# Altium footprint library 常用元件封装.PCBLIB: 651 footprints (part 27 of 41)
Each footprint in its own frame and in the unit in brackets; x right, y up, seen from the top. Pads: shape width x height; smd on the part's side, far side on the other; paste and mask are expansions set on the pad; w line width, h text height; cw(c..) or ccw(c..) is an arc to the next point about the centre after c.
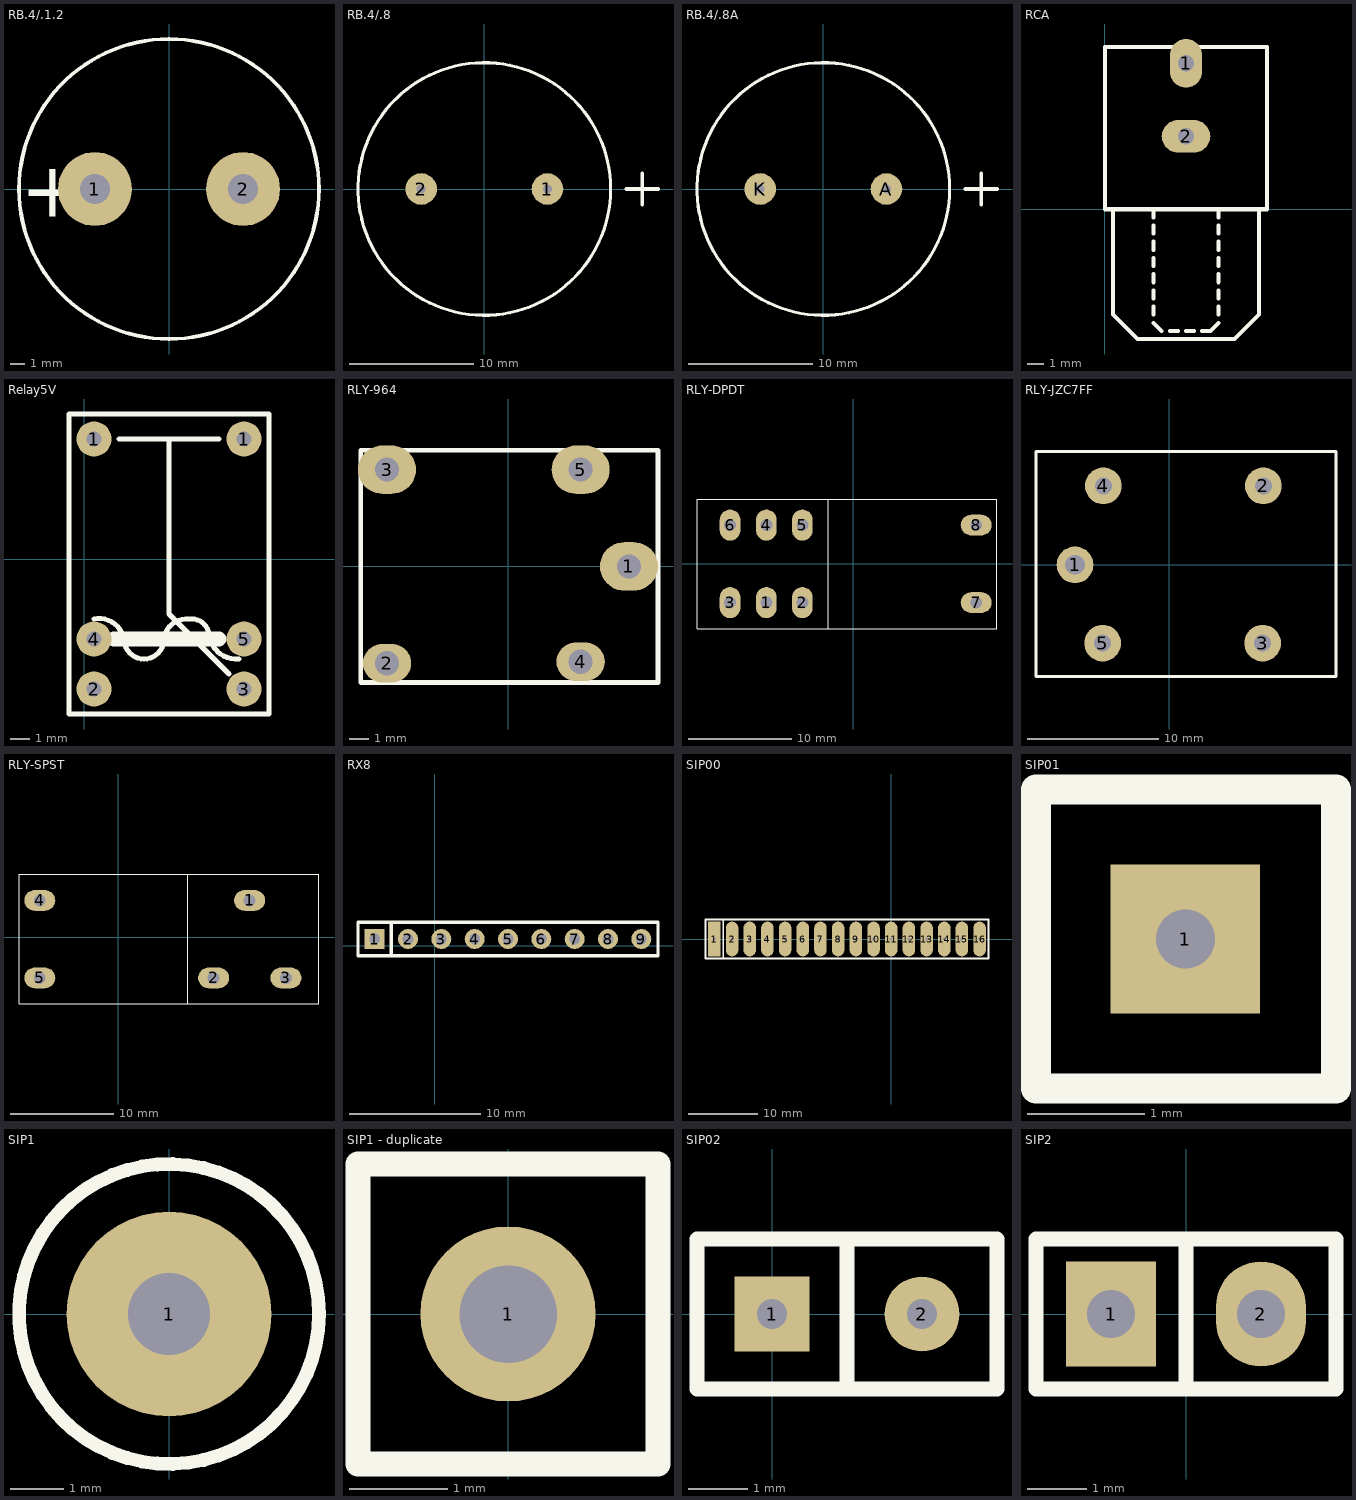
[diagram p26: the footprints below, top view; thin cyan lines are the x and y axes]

## RB.4/.1.2 [mil]
pads (2):
  round 200 hole 80: 1(-200,0) 2(200,0)
TopOverlay:
  circle w10: c0,0 r405.25
  text "+" at -400,-75 h150

## RB.4/.8 [mil]
pads (2):
  round 100 hole 28: 1(200,0) 2(-200,0)
TopOverlay:
  circle w10: c0,0 r400
  lines w12: 450,0 550,0 ; 500,-50 500,50

## RB.4/.8A [mil]
pads (2):
  round 100 hole 28: A(200,0) K(-200,0)
TopOverlay:
  circle w10: c0,0 r400
  lines w12: 450,0 550,0 ; 500,-50 500,50

## RCA [mil]
pads (2):
  oval 80x120 hole 40: 1(200,360)
  oval 120x80 hole 40: 2(200,180)
TopOverlay:
  lines w10: 20,0 20,-260 80,-320 320,-320 380,-260 ; 120,-280 140,-300 ; 120,-260 120,-240 ; 120,-220 120,-200 ; 120,-180 120,-160 ; 120,-140 120,-120 ; 120,-100 120,-80 ; 120,-60 120,-40 ; 120,-20 120,0 ; 160,-300 180,-300 ; 200,-300 220,-300 ; 240,-300 260,-300 280,-280 ; 280,-260 280,-240 ; 280,-220 280,-200 ; 280,-180 280,-160 ; 280,-140 280,-120 ; 280,-100 280,-80 ; 280,-60 280,-40 ; 280,-20 280,0 ; 380,-240 380,-260 ; 380,0 380,-260 ; 0,0 0,400 400,400 400,0 0,0

## Relay5V [mil]
pads (6):
  round 70 hole 30: 1(20,240) 1(320,240) 2(20,-260) 3(320,-260) 4(20,-160) 5(320,-160)
TopOverlay:
  lines w10: 20,-120 cw(c30,-170) 80,-160 ccw(c120,-160) 120,-200 ccw(c120,-160) 160,-160 cw(c205,-165) 210,-120 cw(c215,-155) 250,-150 ccw(c305,-145) 310,-200 ; 70,240 270,240 ; 170,240 170,-110 290,-230 ; -30,-310 -30,290 370,290 370,-310 -30,-310
  lines w30: 60,-160 270,-160

## RLY-964 [mil]
pads (5):
  oval 120x100 hole 50: 1(250,0) 3(-250,200) 5(150,200)
  oval 100x80 hole 50: 2(-250,-200) 4(150,-196.85)
TopOverlay:
  lines w10: -304.17,-240 -304.17,240 310,240 310,0 310,-240 -304.17,-240

## RLY-DPDT [mil]
pads (8):
  oval 79x118 hole 45: 1(-330.5,-147.5) 2(-193.5,-147.5) 3(-468.5,-147.5) 4(-330.5,147.5) 5(-193.5,147.5) 6(-468.5,147.5)
  oval 118x79 hole 45: 7(468.5,-147.5) 8(468.5,147.5)
TopOverlay:
  lines w4: -94.5,-246.5 -94.5,245.5 ; -594.5,-246.5 -594.5,245.5 547.5,245.5 547.5,-246.5 -594.5,-246.5

## RLY-JZC7FF [mm]
pads (5):
  round 2.8 hole 1.5: 1(-7.175,-0.025)
  round 2.8 hole 1.3: 2(7.175,5.994) 3(7.125,-5.994) 4(-5.016,5.994) 5(-5.067,-5.994)
TopOverlay:
  lines w0.254: -10.147,-8.534 -10.147,8.611 12.713,8.611 12.713,-8.534 -10.147,-8.534

## RLY-SPST [mil]
pads (5):
  oval 118x79 hole 45: 1(500,140) 2(363,-155) 3(638,-155) 4(-299,140) 5(-299,-155)
TopOverlay:
  lines w4: 264,-253 264,239 ; -378,-253 764,-253 764,239 -378,239 -378,-253

## RX8 [mil]
pads (9):
  rect 60x60 hole 32: 1(-180,20)
  round 60 hole 32: 2(-80,20) 3(20,20) 4(120,20) 5(220,20) 6(320,20) 7(420,20) 8(520,20) 9(620,20)
TopOverlay:
  lines w10: -130,-30 -130,70 ; -230,-30 -230,70 670,70 670,-30 -230,-30

## SIP00 [mm]
pads (16):
  rect 1.8x5 hole 0.5: 1(-25.4,0)
  oval 1.8x5 hole 0.5: 2(-22.86,0) 3(-20.32,0) 4(-17.78,0) 5(-15.24,0) 6(-12.7,0) 7(-10.16,0) 8(-7.62,0) 9(-5.08,0) 10(-2.54,0) 11(0,0) 12(2.54,0) 13(5.08,0) 14(7.62,0) 15(10.16,0) 16(12.7,0)
TopOverlay:
  lines w0.254: -24.13,-2.794 -24.13,2.794 ; -26.67,-2.794 13.97,-2.794 13.97,2.794 -26.67,2.794 -26.67,-2.794

## SIP01 [mm]
pads (1):
  rect 1.27x1.27 hole 0.5: 1(50.8,101.6)
TopOverlay:
  lines w0.254: 52.06,100.33 49.53,100.33 49.53,102.87 52.07,102.87 ; 52.08,100.33 52.08,102.87

## SIP1 [mil]
pads (1):
  round 150 hole 60: 1(0,0)
TopOverlay:
  circle w10: c0,0 r110

## SIP1 - duplicate [mil]
pads (1):
  round 70 hole 39: 1(0,0)
TopOverlay:
  lines w10: -60,-60 40,-60 60,-60 60,-40 60,60 40,60 -60,60 -60,-40 -60,-60

## SIP02 [mm]
pads (2):
  rect 1.27x1.27 hole 0.5: 1(0,0)
  round 1.27 hole 0.5: 2(2.54,0)
TopOverlay:
  lines w0.254: 1.27,-1.27 1.27,1.27 ; -1.27,-1.27 -1.27,1.27 3.81,1.27 3.81,-1.27 -1.27,-1.27

## SIP2 [mil]
pads (2):
  rect 60x70 hole 32: 1(-50,0)
  oval 60x70 hole 32: 2(50,0)
TopOverlay:
  lines w10: 0,-50 0,50 ; -100,-50 -100,50 100,50 100,-50 -100,-50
